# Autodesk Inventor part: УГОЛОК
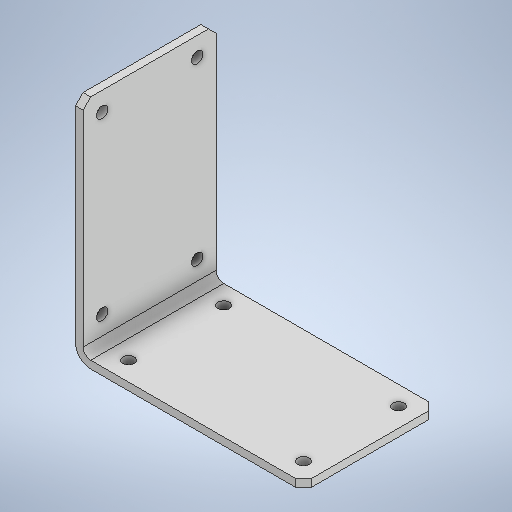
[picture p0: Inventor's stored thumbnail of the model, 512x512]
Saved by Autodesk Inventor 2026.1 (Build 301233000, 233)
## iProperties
Created: 2025-12
Part Number: УГОЛОК
Material: Типовые
Document SubType Name: Modeling
Designer: Yury Melnikov
Density: 1 g/cm^3
Appearance: По умолчанию
Author: Yury Melnikov
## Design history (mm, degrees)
sketch "Эскиз1"
  geometry: L1 (0, 60)-(0, 4); L2 (4, 0)-(60, 0); L3 (2, 60)-(2, 4); L4 (4, 2)-(60, 2); L5 (60, 2)-(60, 0); L6 (2, 60)-(0, 60); A1 r 2 centre (4, 4) between (2, 4) and (4, 2); A2 r 4 centre (4, 4) between (0, 4) and (4, 0); 1 further point
  constraints: 12 end point, 4 perpendicular, 4 point on circle, 4 tangent, 2 centre point, 2 point on line, 2 vertical, 1 concentric, 1 horizontal alignment, 1 vertical alignment, 1 other
  dimensions: "d0" = 2 distance between parallel lines of L1 L3; "d1" = 60 distance of L1.start point (0, 0); "d3" = 2 radius of A1
extrude "Выдавливание1" new body sketch "Эскиз1" distance "d4" = 35; taper "d5" = 0 deg
sketch "Эскиз2"
  geometry: L1 (0, 0)-(0, 56) reference; L2 (0, 56)-(-35, 56) reference; L3 (-35, 0)-(-35, 56) reference; L4 (0, 0)-(-35, 0) reference; L5 (-30, 51)-(-5, 51); L6 (-5, 51)-(-5, 5); L7 (-5, 5)-(-30, 5); L8 (-30, 5)-(-30, 51); C1 r 1.5 at (-30, 51); C2 r 1.5 at (-5, 51); C3 r 1.5 at (-5, 5); C4 r 1.5 at (-30, 5); 1 further point
  constraints: 8 end point, 4 centre point, 4 coincident, 3 equal radius, 3 other
  dimensions: "d6" = 3 diameter of C2; "d7" = 5 distance between parallel lines of L1 L6
extrude "Выдавливание2" cut sketch "Эскиз2" distance "d8" = 35; taper "d9" = 0 deg
pattern_circular "Круговой массив1" dims angle "d11" = 360 deg
chamfer "Фаска1" distance "d13" = 2; stored, may be unused: second distance "d14" = 2, angle "d15" = 45 deg
node "Твердое тело1"
node "Спроецированная петля1"
